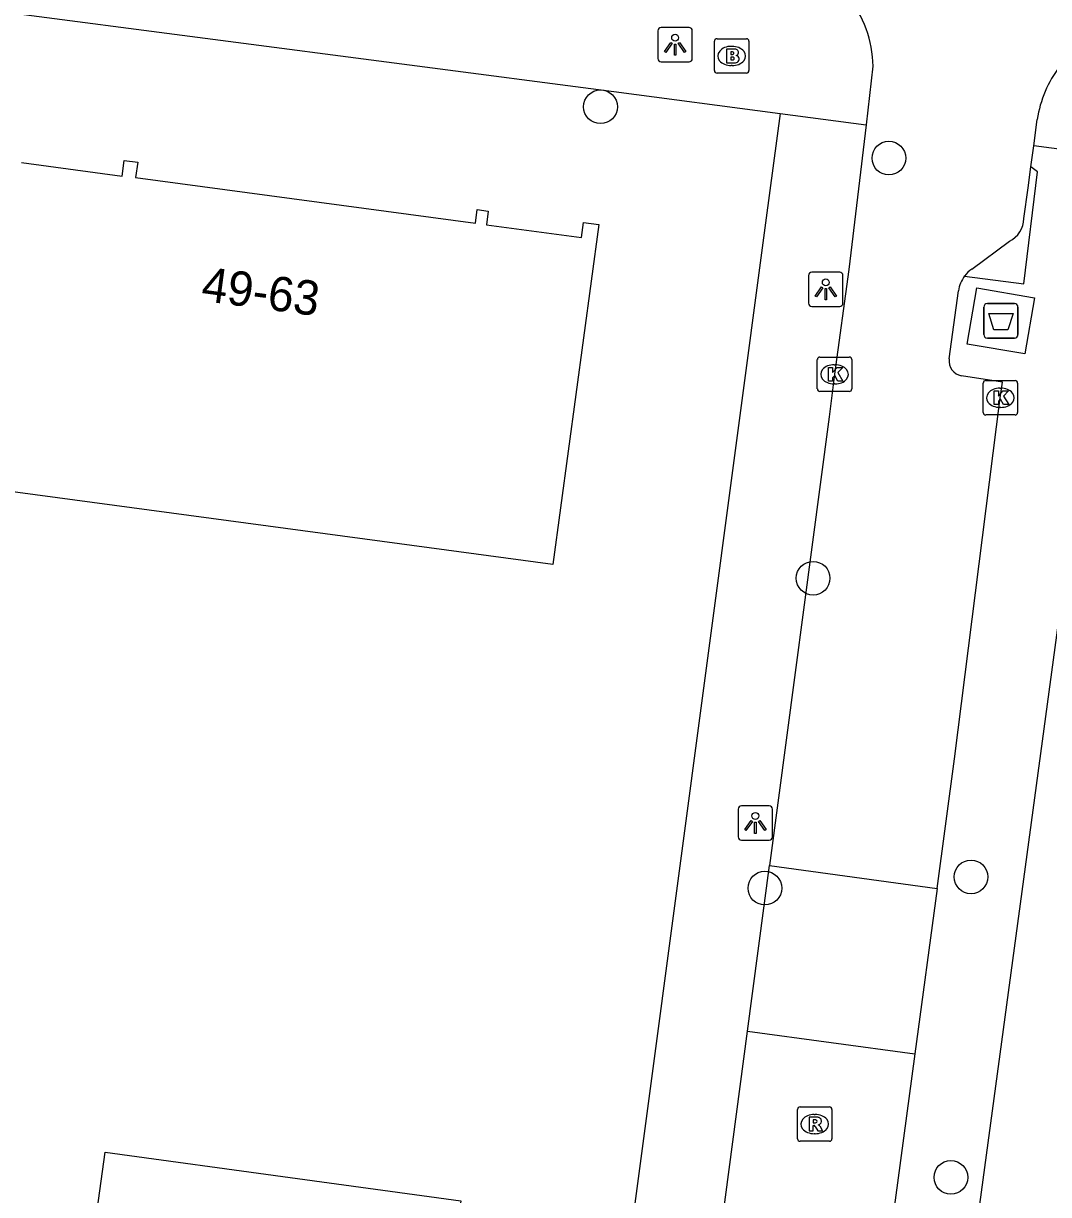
# Model space of a CAD drawing. Extents: x 161258 to 161838, y 380836 to 381727.
# Drawn here: x 161723.34 to 161753.1, y 381610.1 to 381644.11 of the extents above; entities that cross this region are included whole.
import ezdxf

# ---------------------------------------------------------------- set-up
doc = ezdxf.new("R2010")
doc.units = 0
for name, color, linetype in [('IMGEO_Afval_apart_plaats', 7, 'Continuous'), ('IMGEO_Boom', 7, 'Continuous'), ('IMGEO_Brandkraan', 7, 'Continuous'), ('IMGEO_Kolk', 7, 'Continuous'), ('IMGEO_Lichtpunt', 7, 'Continuous'), ('IMGEO_Pand', 7, 'Continuous'), ('IMGEO_Pand_nummerreeks', 7, 'Continuous'), ('IMGEO_Rijbaan_lokaal_open', 7, 'Continuous'), ('IMGEO_Rioolput', 7, 'Continuous'), ('IMGEO_Voetpad_gesloten', 7, 'Continuous'), ('IMGEO_Voetpad_open', 7, 'Continuous')]:
    doc.layers.add(name, color=color, linetype=linetype)

msp = doc.modelspace()

# ---------------------------------------------------------------- linework, layer by layer
at = {"layer": 'IMGEO_Afval_apart_plaats'}
for p, q in [((161751.218, 381635.073), (161751.218, 381635.873)), ((161751.218, 381635.873), (161751.218, 381635.073)), ((161751.318, 381635.973), (161752.108, 381635.973)), ((161752.108, 381635.973), (161751.318, 381635.973)), ((161752.208, 381635.873), (161752.208, 381635.073)), ((161752.208, 381635.073), (161752.208, 381635.873)), ((161752.108, 381634.973), (161751.318, 381634.973)), ((161751.318, 381634.973), (161752.108, 381634.973))]:
    msp.add_line(p, q, dxfattribs=at)
msp.add_lwpolyline([(161751.361, 381635.687), (161752.065, 381635.687), (161751.916, 381635.217), (161751.51, 381635.217), (161751.361, 381635.687)], dxfattribs=at)
for centre, start, end in [((161751.318, 381635.873), 90, 180), ((161751.318, 381635.873), 90, 180), ((161752.108, 381635.873), 0, 90), ((161752.108, 381635.873), 360, 90), ((161751.318, 381635.073), 180, 270), ((161751.318, 381635.073), 180, 270), ((161752.108, 381635.073), 270, 0), ((161752.108, 381635.073), 270, 0)]:
    msp.add_arc(centre, 0.1, start, end, dxfattribs=at)
at = {"layer": 'IMGEO_Boom'}
for centre in [(161740.089, 381641.69), (161748.46, 381640.2), (161746.26, 381628), (161750.844, 381619.326), (161744.86, 381619), (161750.26, 381610.6)]:
    msp.add_circle(centre, 0.489, dxfattribs=at)
at = {"layer": 'IMGEO_Brandkraan'}
for p, q in [((161743.396, 381642.74), (161743.396, 381643.592)), ((161743.471, 381643.666), (161744.323, 381643.666)), ((161744.397, 381643.592), (161744.397, 381642.74)), ((161743.884, 381643.446), (161743.909, 381643.446)), ((161743.907, 381642.886), (161743.882, 381642.886)), ((161744.323, 381642.666), (161743.471, 381642.666))]:
    msp.add_line(p, q, dxfattribs=at)
for points in [[(161743.396, 381642.74), (161743.396, 381643.592)], [(161743.471, 381643.666), (161744.323, 381643.666)], [(161744.397, 381643.592), (161744.397, 381642.74)], [(161743.744, 381643.366), (161743.744, 381642.966), (161743.957, 381642.966)], [(161743.975, 381643.366), (161743.744, 381643.366)], [(161743.923, 381643.285), (161743.869, 381643.285), (161743.869, 381643.209)], [(161743.869, 381643.209), (161743.922, 381643.209)], [(161743.931, 381643.133), (161743.869, 381643.133), (161743.869, 381643.052)], [(161743.869, 381643.052), (161743.931, 381643.052)], [(161744.323, 381642.666), (161743.471, 381642.666)]]:
    msp.add_lwpolyline(points, dxfattribs=at)
for centre, radius, start, end in [((161743.473, 381643.59), 0.0765, 91.552, 178.448), ((161743.473, 381643.59), 0.0765, 91.552, 178.448), ((161744.321, 381643.59), 0.0765, 1.552, 88.448), ((161744.321, 381643.59), 0.0765, 1.552, 88.448), ((161743.924, 381643.247), 0.0379, 267.8285, 90.9355), ((161743.979, 381643.221), 0.145, 59.4692, 91.5367), ((161744.004, 381643.268), 0.0922, 285.5137, 58.1501), ((161743.932, 381643.092), 0.0404, 269.8759, 90.5077), ((161743.963, 381643.217), 0.251, 268.6676, 293.5347), ((161744.009, 381643.076), 0.105, 301.3115, 78.989), ((161743.473, 381642.742), 0.0765, 181.552, 268.448), ((161743.473, 381642.742), 0.0765, 181.552, 268.448), ((161744.321, 381642.742), 0.0765, 271.552, 358.448), ((161744.321, 381642.742), 0.0765, 271.552, 358.448)]:
    msp.add_arc(centre, radius, start, end, dxfattribs=at)
for centre, major_axis, ratio, start_param, end_param in [((161743.883, 381643.166), (-0.387, 0.002), 0.722429, 4.712389, 7.853982), ((161743.908, 381643.166), (-0.39, 0.002), 0.717154, 1.570796, 4.712389)]:
    msp.add_ellipse(centre, major_axis=major_axis, ratio=ratio, start_param=start_param, end_param=end_param, dxfattribs=at)
at = {"layer": 'IMGEO_Kolk'}
for p, q in [((161746.458, 381634.421), (161747.31, 381634.421)), ((161746.383, 381633.495), (161746.383, 381634.347)), ((161746.871, 381634.201), (161746.896, 381634.201)), ((161747.384, 381634.347), (161747.384, 381633.495)), ((161751.27, 381633.74), (161752.122, 381633.74)), ((161747.31, 381633.421), (161746.458, 381633.421)), ((161746.894, 381633.641), (161746.869, 381633.641)), ((161751.195, 381632.814), (161751.195, 381633.666)), ((161751.683, 381633.52), (161751.708, 381633.52)), ((161752.196, 381633.666), (161752.196, 381632.814)), ((161752.122, 381632.74), (161751.27, 381632.74)), ((161751.706, 381632.96), (161751.681, 381632.96))]:
    msp.add_line(p, q, dxfattribs=at)
for points in [[(161746.458, 381634.421), (161747.31, 381634.421)], [(161746.383, 381633.495), (161746.383, 381634.347)], [(161746.704, 381634.121), (161746.827, 381634.121), (161746.827, 381633.97), (161746.957, 381634.121), (161747.121, 381634.121), (161746.975, 381633.97), (161747.128, 381633.721), (161746.976, 381633.721), (161746.891, 381633.885), (161746.827, 381633.818), (161746.827, 381633.721), (161746.704, 381633.721), (161746.704, 381634.121)], [(161747.384, 381634.347), (161747.384, 381633.495)], [(161751.27, 381633.74), (161752.122, 381633.74)], [(161747.31, 381633.421), (161746.458, 381633.421)], [(161751.195, 381632.814), (161751.195, 381633.666)], [(161751.516, 381633.44), (161751.639, 381633.44), (161751.639, 381633.289), (161751.769, 381633.44), (161751.933, 381633.44), (161751.787, 381633.289), (161751.94, 381633.04), (161751.788, 381633.04), (161751.703, 381633.204), (161751.639, 381633.137), (161751.639, 381633.04), (161751.516, 381633.04), (161751.516, 381633.44)], [(161752.196, 381633.666), (161752.196, 381632.814)], [(161752.122, 381632.74), (161751.27, 381632.74)]]:
    msp.add_lwpolyline(points, dxfattribs=at)
for centre, start, end in [((161746.46, 381634.345), 91.552, 178.448), ((161746.46, 381634.345), 91.552, 178.448), ((161747.308, 381634.345), 1.552, 88.448), ((161747.308, 381634.345), 1.552, 88.448), ((161751.272, 381633.664), 91.552, 178.448), ((161751.272, 381633.664), 91.552, 178.448), ((161752.12, 381633.664), 1.552, 88.448), ((161752.12, 381633.664), 1.552, 88.448), ((161746.46, 381633.497), 181.552, 268.448), ((161746.46, 381633.497), 181.552, 268.448), ((161747.308, 381633.497), 271.552, 358.448), ((161747.308, 381633.497), 271.552, 358.448), ((161751.272, 381632.816), 181.552, 268.448), ((161751.272, 381632.816), 181.552, 268.448), ((161752.12, 381632.816), 271.552, 358.448), ((161752.12, 381632.816), 271.552, 358.448)]:
    msp.add_arc(centre, 0.0765, start, end, dxfattribs=at)
for centre, major_axis, ratio, start_param, end_param in [((161746.87, 381633.921), (-0.387, 0.002), 0.722429, 4.712389, 7.853982), ((161746.895, 381633.921), (-0.39, 0.002), 0.717154, 1.570796, 4.712389), ((161751.682, 381633.24), (-0.387, 0.002), 0.722429, 4.712389, 7.853982), ((161751.707, 381633.24), (-0.39, 0.002), 0.717154, 1.570796, 4.712389)]:
    msp.add_ellipse(centre, major_axis=major_axis, ratio=ratio, start_param=start_param, end_param=end_param, dxfattribs=at)
at = {"layer": 'IMGEO_Lichtpunt'}
for p, q in [((161742.659, 381643.992), (161741.851, 381643.992)), ((161742.659, 381643.992), (161741.851, 381643.992)), ((161741.757, 381643.897), (161741.757, 381643.09)), ((161741.757, 381643.897), (161741.757, 381643.09)), ((161742.753, 381643.09), (161742.753, 381643.897)), ((161742.753, 381643.09), (161742.753, 381643.897)), ((161741.851, 381642.996), (161742.659, 381642.996)), ((161741.851, 381642.996), (161742.659, 381642.996)), ((161746.13, 381636.794), (161746.13, 381635.987)), ((161746.13, 381636.794), (161746.13, 381635.987)), ((161747.032, 381636.889), (161746.224, 381636.889)), ((161747.032, 381636.889), (161746.224, 381636.889)), ((161747.126, 381635.987), (161747.126, 381636.794)), ((161747.126, 381635.987), (161747.126, 381636.794)), ((161746.224, 381635.893), (161747.032, 381635.893)), ((161746.224, 381635.893), (161747.032, 381635.893)), ((161744.087, 381621.297), (161744.087, 381620.49)), ((161744.087, 381621.297), (161744.087, 381620.49)), ((161744.989, 381621.392), (161744.181, 381621.392)), ((161744.989, 381621.392), (161744.181, 381621.392)), ((161745.083, 381620.49), (161745.083, 381621.297)), ((161745.083, 381620.49), (161745.083, 381621.297)), ((161744.181, 381620.396), (161744.989, 381620.396)), ((161744.181, 381620.396), (161744.989, 381620.396))]:
    msp.add_line(p, q, dxfattribs=at)
for points in [[(161742.131, 381643.561), (161742.17, 381643.533), (161741.982, 381643.271), (161741.944, 381643.298), (161742.131, 381643.561)], [(161742.233, 381643.513), (161742.28, 381643.513), (161742.28, 381643.191), (161742.233, 381643.191), (161742.233, 381643.513)], [(161742.343, 381643.533), (161742.381, 381643.56), (161742.568, 381643.298), (161742.529, 381643.27), (161742.343, 381643.533)], [(161746.504, 381636.458), (161746.543, 381636.43), (161746.355, 381636.168), (161746.317, 381636.195), (161746.504, 381636.458)], [(161746.716, 381636.43), (161746.754, 381636.457), (161746.941, 381636.195), (161746.902, 381636.167), (161746.716, 381636.43)], [(161746.606, 381636.41), (161746.653, 381636.41), (161746.653, 381636.088), (161746.606, 381636.088), (161746.606, 381636.41)], [(161744.461, 381620.961), (161744.5, 381620.933), (161744.312, 381620.671), (161744.274, 381620.698), (161744.461, 381620.961)], [(161744.563, 381620.913), (161744.61, 381620.913), (161744.61, 381620.591), (161744.563, 381620.591), (161744.563, 381620.913)], [(161744.673, 381620.933), (161744.711, 381620.96), (161744.898, 381620.698), (161744.859, 381620.67), (161744.673, 381620.933)]]:
    msp.add_lwpolyline(points, dxfattribs=at)
for centre in [(161742.256, 381643.695), (161746.629, 381636.592), (161744.586, 381621.095)]:
    msp.add_circle(centre, 0.0994, dxfattribs=at)
for centre, start, end in [((161741.851, 381643.897), 90, 180), ((161741.851, 381643.897), 90, 180), ((161742.659, 381643.897), 0, 90), ((161742.659, 381643.897), 0, 90), ((161741.851, 381643.09), 180, 270), ((161741.851, 381643.09), 180, 270), ((161742.659, 381643.09), 270, 0), ((161742.659, 381643.09), 270, 360), ((161746.224, 381636.794), 90, 180), ((161746.224, 381636.794), 90, 180), ((161747.032, 381636.794), 0, 90), ((161747.032, 381636.794), 0, 90), ((161746.224, 381635.987), 180, 270), ((161746.224, 381635.987), 180, 270), ((161747.032, 381635.987), 270, 0), ((161747.032, 381635.987), 270, 360), ((161744.181, 381621.297), 90, 180), ((161744.181, 381621.297), 90, 180), ((161744.989, 381621.297), 0, 90), ((161744.989, 381621.297), 0, 90), ((161744.181, 381620.49), 180, 270), ((161744.181, 381620.49), 180, 270), ((161744.989, 381620.49), 270, 0), ((161744.989, 381620.49), 270, 360)]:
    msp.add_arc(centre, 0.0946, start, end, dxfattribs=at)
at = {"layer": 'IMGEO_Pand'}
for points in [[(161723.281, 381640.073), (161726.205, 381639.679), (161726.266, 381640.131), (161726.654, 381640.079), (161726.594, 381639.634), (161736.456, 381638.306), (161736.51, 381638.705), (161736.829, 381638.662), (161736.776, 381638.265), (161739.537, 381637.893), (161739.596, 381638.332), (161740.038, 381638.273), (161738.708, 381628.4), (161733.754, 381629.067), (161722.012, 381630.648)], [(161724.852, 381605.092), (161725.709, 381611.334), (161731.083, 381610.597), (161736.036, 381609.917), (161735.957, 381609.341), (161736.595, 381608.501), (161736.372, 381606.876), (161735.502, 381606.216), (161735.153, 381603.676)]]:
    msp.add_lwpolyline(points, dxfattribs=at)
at = {"layer": 'IMGEO_Rijbaan_lokaal_open'}
for points in [[(161747.999, 381642.867), (161747.796, 381641.17)], [(161752.667, 381640.554), (161752.769, 381641.323)], [(161747.796, 381641.17), (161747.293, 381636.965), (161746.885, 381633.921), (161746.729, 381632.69), (161744.994, 381619.655)], [(161752.584, 381639.949), (161752.667, 381640.554)], [(161752.376, 381638.444), (161752.501, 381639.339), (161752.584, 381639.949)], [(161750.868, 381636.979), (161751.957, 381637.783)], [(161750.212, 381634.369), (161750.478, 381636.344)], [(161749.866, 381618.991), (161750.369, 381622.752), (161751.695, 381633.24), (161751.755, 381633.691), (161750.568, 381633.878)], [(161744.354, 381614.846), (161744.994, 381619.655)], [(161744.994, 381619.655), (161749.866, 381618.991)], [(161749.866, 381618.991), (161749.217, 381614.192)], [(161739.855, 381581.833), (161740.814, 381588.417), (161742.995, 381604.548), (161744.354, 381614.846)], [(161744.354, 381614.846), (161749.217, 381614.192)], [(161749.217, 381614.192), (161747.81, 381603.742), (161745.701, 381588.26), (161744.935, 381582.525), (161744.761, 381581.189)]]:
    msp.add_lwpolyline(points, dxfattribs=at)
for centre, radius, start, end in [((161744.742, 381642.833), 3.258, 0.6006, 39.4785), ((161756.027, 381640.852), 3.292, 142.367, 171.7761), ((161751.63, 381638.454), 0.746, 296.0034, 359.2564), ((161751.422, 381636.203), 0.954, 143.0604, 171.474), ((161751.412, 381636.209), 0.943, 125.2769, 143.0544), ((161750.641, 381634.306), 0.434, 171.6197, 260.2683)]:
    msp.add_arc(centre, radius, start, end, dxfattribs=at)
at = {"layer": 'IMGEO_Rioolput'}
for p, q in [((161745.881, 381612.648), (161746.733, 381612.648)), ((161745.806, 381611.722), (161745.806, 381612.574)), ((161746.294, 381612.428), (161746.319, 381612.428)), ((161746.807, 381612.574), (161746.807, 381611.722)), ((161746.733, 381611.648), (161745.881, 381611.648)), ((161746.317, 381611.868), (161746.292, 381611.868))]:
    msp.add_line(p, q, dxfattribs=at)
for points in [[(161745.881, 381612.648), (161746.733, 381612.648)], [(161745.806, 381611.722), (161745.806, 381612.574)], [(161746.395, 381612.346), (161746.143, 381612.348), (161746.143, 381611.948)], [(161746.807, 381612.574), (161746.807, 381611.722)], [(161746.143, 381611.948), (161746.267, 381611.948), (161746.267, 381612.11), (161746.278, 381612.11)], [(161746.321, 381612.267), (161746.267, 381612.267), (161746.267, 381612.186)], [(161746.267, 381612.186), (161746.319, 381612.186)], [(161746.325, 381612.081), (161746.396, 381611.948), (161746.536, 381611.948), (161746.471, 381612.074)], [(161746.733, 381611.648), (161745.881, 381611.648)]]:
    msp.add_lwpolyline(points, dxfattribs=at)
for centre, radius, start, end in [((161745.883, 381612.572), 0.0765, 91.552, 178.448), ((161745.883, 381612.572), 0.0765, 91.552, 178.448), ((161746.731, 381612.572), 0.0765, 1.552, 88.448), ((161746.731, 381612.572), 0.0765, 1.552, 88.448), ((161746.394, 381612.236), 0.109, 350.3612, 89.416), ((161746.277, 381612.057), 0.0533, 26.0293, 88.6989), ((161746.303, 381612.375), 0.19, 274.7715, 282.9687), ((161746.327, 381612.171), 0.0964, 77.0061, 93.1865), ((161746.341, 381612.228), 0.0378, 276.6634, 79.6772), ((161746.392, 381612.236), 0.112, 277.5842, 350.9817), ((161746.376, 381612.021), 0.108, 29.5134, 73.7905), ((161745.883, 381611.724), 0.0765, 181.552, 268.448), ((161745.883, 381611.724), 0.0765, 181.552, 268.448), ((161746.731, 381611.724), 0.0765, 271.552, 358.448), ((161746.731, 381611.724), 0.0765, 271.552, 358.448)]:
    msp.add_arc(centre, radius, start, end, dxfattribs=at)
for centre, major_axis, ratio, start_param, end_param in [((161746.293, 381612.148), (-0.387, 0.002), 0.722429, 4.712389, 7.853982), ((161746.318, 381612.148), (-0.39, 0.002), 0.717154, 1.570796, 4.712389)]:
    msp.add_ellipse(centre, major_axis=major_axis, ratio=ratio, start_param=start_param, end_param=end_param, dxfattribs=at)
at = {"layer": 'IMGEO_Voetpad_gesloten'}
msp.add_lwpolyline([(161750.735, 381634.801), (161751.016, 381636.433), (161752.691, 381636.145), (161752.41, 381634.513), (161750.735, 381634.801)], dxfattribs=at)
at = {"layer": 'IMGEO_Voetpad_open'}
for points in [[(161599.202, 381661.023), (161611.247, 381659.449), (161663.105, 381652.447), (161684.01, 381649.696), (161716.743, 381645.239), (161740.472, 381642.131), (161745.302, 381641.497)], [(161745.302, 381641.497), (161744.895, 381638.467), (161737.106, 381579.978)], [(161745.302, 381641.497), (161747.796, 381641.17)], [(161755.234, 381640.215), (161752.667, 381640.554)], [(161749.372, 381596.944), (161750.063, 381602.151), (161754.739, 381636.721), (161755.234, 381640.215)], [(161750.659, 381636.776), (161752.376, 381636.547), (161752.771, 381639.8), (161752.584, 381639.949)]]:
    msp.add_lwpolyline(points, dxfattribs=at)

# ---------------------------------------------------------------- texts
at = {"layer": 'IMGEO_Pand_nummerreeks'}
msp.add_text('49-63', height=1, rotation=352.4646, dxfattribs=at).set_placement((161728.471, 381636.059))

doc.saveas('drawing.dxf')
